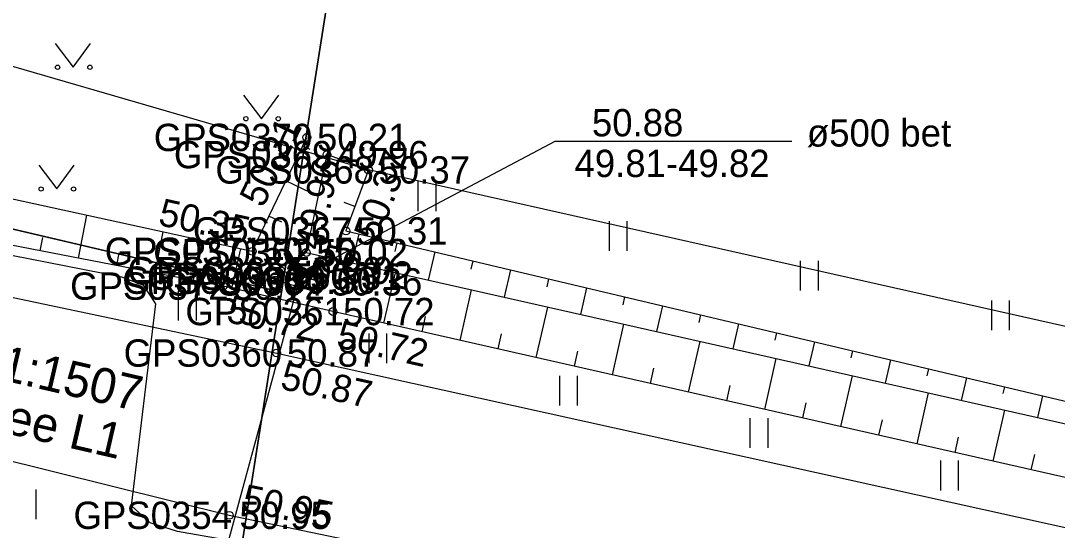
# Model space of a CAD drawing. Extents: x 551623 to 559850, y 6561220 to 6567135.
# Drawn here: x 555686.72 to 555713.27, y 6565381.27 to 6565394.32 of the extents above; entities that cross this region are included whole.
import ezdxf

# ---------------------------------------------------------------- set-up
doc = ezdxf.new("R2010")
doc.units = 0
for name, color, linetype in [('HALJASTUS', 7, 'Continuous'), ('KORGUS-EH2000', 7, 'Continuous'), ('MOOTKORG-EH2000', 7, 'Continuous'), ('MOOTMPUNKT', 7, 'Continuous'), ('MOOTNR', 7, 'Continuous'), ('MOOTPIIR', 7, 'Continuous'), ('MPKAABEL', 7, 'Continuous'), ('PIIR', 7, 'Continuous'), ('RELJEEF', 7, 'Continuous'), ('TEE', 7, 'Continuous'), ('TRUUP', 7, 'Continuous')]:
    doc.layers.add(name, color=color, linetype=linetype)

msp = doc.modelspace()

# ---------------------------------------------------------------- linework, layer by layer
at = {"layer": 'HALJASTUS'}
for p, q in [((555687.602, 6565393.734), (555688.066, 6565393.127)), ((555688.066, 6565393.127), (555688.511, 6565393.734)), ((555692.425, 6565392.416), (555692.889, 6565391.809)), ((555692.889, 6565391.809), (555693.334, 6565392.416)), ((555687.183, 6565390.618), (555687.646, 6565390.011)), ((555687.646, 6565390.011), (555688.092, 6565390.618)), ((555696.897, 6565390.204), (555696.897, 6565389.443)), ((555697.352, 6565390.204), (555697.352, 6565389.443)), ((555701.793, 6565389.189), (555701.793, 6565388.428)), ((555702.248, 6565389.189), (555702.248, 6565388.428)), ((555706.689, 6565388.173), (555706.689, 6565387.412)), ((555707.144, 6565388.173), (555707.144, 6565387.412)), ((555690.758, 6565387.402), (555690.758, 6565386.641)), ((555691.213, 6565387.402), (555691.213, 6565386.641)), ((555711.584, 6565387.158), (555711.584, 6565386.397)), ((555712.04, 6565387.158), (555712.04, 6565386.397)), ((555695.638, 6565386.31), (555695.638, 6565385.549)), ((555696.093, 6565386.31), (555696.093, 6565385.549)), ((555700.519, 6565385.225), (555700.519, 6565384.464)), ((555700.974, 6565385.225), (555700.974, 6565384.464)), ((555705.399, 6565384.14), (555705.399, 6565383.379)), ((555705.854, 6565384.14), (555705.854, 6565383.379)), ((555710.28, 6565383.055), (555710.28, 6565382.294)), ((555710.735, 6565383.055), (555710.735, 6565382.294)), ((555687.109, 6565382.317), (555687.109, 6565381.556))]:
    msp.add_line(p, q, dxfattribs=at)
for centre in [(555687.665, 6565393.127), (555688.493, 6565393.127), (555692.488, 6565391.809), (555693.317, 6565391.809), (555687.245, 6565390.011), (555688.074, 6565390.011)]:
    msp.add_circle(centre, 0.055, dxfattribs=at)
at = {"layer": 'KORGUS-EH2000'}
for centre in [(555694.05, 6565391.331), (555694.565, 6565390.891), (555695.628, 6565390.499), (555692.652, 6565388.415), (555694.035, 6565388.383), (555691.907, 6565387.524), (555694.718, 6565386.873), (555693.278, 6565385.81), (555692.063, 6565381.655)]:
    msp.add_circle(centre, 0.1, dxfattribs=at)
at = {"layer": 'MOOTMPUNKT'}
for centre in [(555694.05, 6565391.331), (555694.565, 6565390.891), (555695.628, 6565390.499), (555695.052, 6565388.937), (555692.652, 6565388.415), (555694.035, 6565388.383), (555693.378, 6565387.919), (555693.875, 6565387.778), (555691.907, 6565387.524), (555693.243, 6565387.677), (555694.404, 6565387.632), (555694.718, 6565386.873), (555693.278, 6565385.81), (555692.063, 6565381.655)]:
    msp.add_circle(centre, 0.1, dxfattribs=at)
at = {"layer": 'MOOTPIIR'}
msp.add_lwpolyline([(555870.644, 6565361.764), (555852.219, 6565361.421), (555851.243, 6565363.431), (555851.072, 6565365.834), (555850.919, 6565369.424), (555850.689, 6565372.676), (555824.92, 6565373.681), (555819.298, 6565374.346), (555817.733, 6565372.559), (555794.391, 6565373.752), (555774.303, 6565374.86), (555767.052, 6565376.433), (555763.583, 6565376.705), (555741.853, 6565379.526), (555720.243, 6565384.972), (555695.628, 6565390.499), (555681.099, 6565394.714), (555669.53, 6565398.005), (555662.804, 6565398.822)], dxfattribs=at)
at = {"layer": 'MPKAABEL'}
msp.add_lwpolyline([(555754.809, 6565368.578), (555745.82, 6565370.031), (555736.449, 6565371.941), (555727.141, 6565373.859), (555717.551, 6565375.859), (555708.191, 6565377.73), (555698.129, 6565379.941), (555690.738, 6565381.238), (555690.039, 6565381.461), (555689.559, 6565381.898), (555690.18, 6565387.07), (555689.871, 6565387.539), (555689.309, 6565387.75), (555680.781, 6565389.43), (555671.469, 6565391.391), (555661.898, 6565393.719)], dxfattribs=at)
at = {"layer": 'PIIR'}
for points in [[(555584.65, 6565412.91), (555612.09, 6565586.3), (555722.09, 6565569.1), (555693.4, 6565387.37)], [(555693.4, 6565387.37), (555722.09, 6565569.1), (555756.75, 6565564.43), (555823.05, 6565554.69), (555792.17, 6565359.86), (555785.15, 6565359.9), (555766.77, 6565362.31), (555692.03, 6565378.6)], [(555443.35, 6565442.49), (555368.05, 6565461.11), (555419.74, 6565450.66), (555470.4, 6565439.4), (555495.41, 6565433.85), (555584.65, 6565412.91), (555693.4, 6565387.37), (555692.03, 6565378.6), (555540.46, 6565411.94), (555441.38, 6565433.61)]]:
    msp.add_lwpolyline(points, close=True, dxfattribs=at)
at = {"layer": 'RELJEEF'}
for p, q in [((555692.652, 6565388.415), (555694.05, 6565391.331)), ((555693.949, 6565391.12), (555694.13, 6565391.034)), ((555695.628, 6565390.499), (555694.565, 6565390.891)), ((555693.517, 6565390.219), (555694.34, 6565389.824)), ((555695.282, 6565389.561), (555695.004, 6565389.663)), ((555688.202, 6565388.239), (555688.415, 6565389.34)), ((555693.084, 6565389.317), (555693.397, 6565389.167)), ((555690.166, 6565387.86), (555690.369, 6565388.913)), ((555687.22, 6565388.428), (555687.285, 6565388.766)), ((555695.378, 6565388.86), (555695.203, 6565388.119)), ((555696.352, 6565388.63), (555696.3, 6565388.411)), ((555689.184, 6565388.049), (555689.246, 6565388.372)), ((555692.128, 6565387.472), (555692.361, 6565388.479)), ((555697.325, 6565388.399), (555697.154, 6565387.679)), ((555694.229, 6565387.681), (555694.373, 6565388.306)), ((555698.298, 6565388.169), (555698.247, 6565387.956)), ((555691.148, 6565387.67), (555691.207, 6565387.979)), ((555696.026, 6565386.577), (555696.319, 6565387.868)), ((555699.271, 6565387.939), (555699.105, 6565387.239)), ((555700.244, 6565387.708), (555700.195, 6565387.502)), ((555694.076, 6565387.022), (555694.168, 6565387.418)), ((555697.977, 6565386.135), (555698.27, 6565387.428)), ((555701.217, 6565387.478), (555701.056, 6565386.799)), ((555695.051, 6565386.798), (555695.139, 6565387.185)), ((555702.19, 6565387.248), (555702.143, 6565387.047)), ((555703.163, 6565387.017), (555703.007, 6565386.359)), ((555699.927, 6565385.693), (555700.221, 6565386.987)), ((555704.136, 6565386.787), (555704.09, 6565386.593)), ((555697.002, 6565386.356), (555697.089, 6565386.743)), ((555701.878, 6565385.251), (555702.172, 6565386.547)), ((555705.11, 6565386.557), (555704.959, 6565385.919)), ((555698.952, 6565385.914), (555699.04, 6565386.302)), ((555706.083, 6565386.326), (555706.038, 6565386.138)), ((555703.829, 6565384.81), (555704.123, 6565386.107)), ((555707.056, 6565386.096), (555706.91, 6565385.479)), ((555700.903, 6565385.472), (555700.991, 6565385.861)), ((555708.029, 6565385.866), (555707.986, 6565385.683)), ((555705.779, 6565384.368), (555706.073, 6565385.667)), ((555709.002, 6565385.635), (555708.861, 6565385.038)), ((555702.853, 6565385.031), (555702.941, 6565385.42)), ((555707.73, 6565383.926), (555708.024, 6565385.227)), ((555709.975, 6565385.405), (555709.933, 6565385.229)), ((555710.948, 6565385.175), (555710.812, 6565384.598)), ((555704.804, 6565384.589), (555704.892, 6565384.978)), ((555711.921, 6565384.944), (555711.881, 6565384.774)), ((555709.68, 6565383.484), (555709.975, 6565384.787)), ((555712.894, 6565384.714), (555712.763, 6565384.158)), ((555706.755, 6565384.147), (555706.843, 6565384.537)), ((555708.705, 6565383.705), (555708.794, 6565384.096)), ((555711.631, 6565383.042), (555711.926, 6565384.347)), ((555710.656, 6565383.263), (555710.744, 6565383.654)), ((555712.606, 6565382.822), (555712.695, 6565383.213))]:
    msp.add_line(p, q, dxfattribs=at)
for points in [[(555670.328, 6565392.887), (555679.228, 6565391.344), (555692.652, 6565388.415)], [(555695.628, 6565390.499), (555695.052, 6565388.937), (555720.222, 6565382.979), (555741.364, 6565378.247), (555757.349, 6565375.192), (555755.723, 6565374.838), (555741.151, 6565377.01), (555719.315, 6565381.302), (555694.718, 6565386.873), (555691.907, 6565387.524), (555678.96, 6565390.023), (555670.827, 6565391.88), (555670.328, 6565392.887)], [(555694.565, 6565390.891), (555694.035, 6565388.383), (555719.805, 6565382.57), (555741.241, 6565377.86), (555757.349, 6565375.192)]]:
    msp.add_lwpolyline(points, dxfattribs=at)
at = {"layer": 'TEE'}
for points in [[(555463.469, 6565434.873), (555479.318, 6565431.962), (555490.115, 6565429.76), (555497.95, 6565427.828), (555519.263, 6565422.564), (555542.613, 6565417.073), (555565.599, 6565412.035), (555589.51, 6565406.357), (555610.656, 6565401.422), (555635.154, 6565395.619), (555656.789, 6565389.809), (555677.01, 6565385.399), (555692.063, 6565381.655), (555718.607, 6565376.133), (555737.61, 6565372.216), (555759.321, 6565368.781), (555773.34, 6565367.27), (555785.196, 6565366.246), (555799.302, 6565365.674), (555824.141, 6565365.476), (555838.654, 6565365.624), (555851.072, 6565365.834)], [(555669.53, 6565398.005), (555669.393, 6565393.924), (555669.794, 6565392.158), (555670.453, 6565390.974), (555678.315, 6565388.964), (555693.278, 6565385.81), (555719.15, 6565380.087), (555738.319, 6565376.143), (555759.458, 6565372.557), (555763.069, 6565372.038), (555773.873, 6565370.985), (555785.453, 6565370.072), (555799.764, 6565369.552), (555819.003, 6565369.583), (555821.106, 6565370.429), (555821.559, 6565371.986), (555822.022, 6565373.687)]]:
    msp.add_lwpolyline(points, dxfattribs=at)
at = {"layer": 'TRUUP'}
for p, q in [((555693.585, 6565388.427), (555693.461, 6565388.356)), ((555693.461, 6565388.356), (555693.848, 6565387.681)), ((555693.487, 6565388.371), (555693.49, 6565388.305)), ((555693.511, 6565388.385), (555693.518, 6565388.257)), ((555693.523, 6565388.391), (555693.875, 6565387.778)), ((555693.535, 6565388.398), (555693.545, 6565388.209)), ((555693.559, 6565388.412), (555693.573, 6565388.161)), ((555693.584, 6565388.426), (555693.601, 6565388.113)), ((555693.585, 6565388.427), (555693.901, 6565387.875)), ((555693.611, 6565388.38), (555693.628, 6565388.064)), ((555693.639, 6565388.332), (555693.656, 6565388.016)), ((555693.666, 6565388.284), (555693.683, 6565387.968)), ((555693.694, 6565388.236), (555693.711, 6565387.92)), ((555693.722, 6565388.188), (555693.739, 6565387.872)), ((555693.749, 6565388.139), (555693.766, 6565387.823)), ((555693.777, 6565388.091), (555693.794, 6565387.775)), ((555693.875, 6565387.778), (555694.488, 6565388.13)), ((555693.901, 6565387.875), (555694.453, 6565388.191)), ((555694.278, 6565388.091), (555694.286, 6565387.932)), ((555694.302, 6565388.105), (555694.311, 6565387.946)), ((555694.326, 6565388.119), (555694.335, 6565387.96)), ((555694.351, 6565388.133), (555694.359, 6565387.974)), ((555694.375, 6565388.147), (555694.383, 6565387.988)), ((555694.399, 6565388.161), (555694.408, 6565388.002)), ((555694.423, 6565388.175), (555694.432, 6565388.016)), ((555694.448, 6565388.189), (555694.456, 6565388.03)), ((555694.453, 6565388.191), (555694.523, 6565388.068)), ((555694.475, 6565388.153), (555694.481, 6565388.043)), ((555694.502, 6565388.105), (555694.505, 6565388.057)), ((555693.805, 6565388.043), (555693.822, 6565387.727)), ((555693.832, 6565387.995), (555693.849, 6565387.681)), ((555693.848, 6565387.681), (555694.523, 6565388.068)), ((555693.86, 6565387.947), (555693.873, 6565387.695)), ((555693.888, 6565387.898), (555693.898, 6565387.709)), ((555693.913, 6565387.882), (555693.922, 6565387.723)), ((555693.938, 6565387.896), (555693.946, 6565387.737)), ((555693.962, 6565387.91), (555693.971, 6565387.751)), ((555693.986, 6565387.924), (555693.995, 6565387.765)), ((555694.011, 6565387.938), (555694.019, 6565387.779)), ((555694.035, 6565387.952), (555694.043, 6565387.793)), ((555694.059, 6565387.966), (555694.068, 6565387.807)), ((555694.083, 6565387.98), (555694.092, 6565387.821)), ((555694.108, 6565387.994), (555694.116, 6565387.835)), ((555694.132, 6565388.008), (555694.141, 6565387.848)), ((555694.156, 6565388.022), (555694.165, 6565387.862)), ((555694.181, 6565388.036), (555694.189, 6565387.876)), ((555694.205, 6565388.049), (555694.213, 6565387.89)), ((555694.229, 6565388.063), (555694.238, 6565387.904)), ((555694.253, 6565388.077), (555694.262, 6565387.918)), ((555693.875, 6565387.78), (555691.37, 6565378.542))]:
    msp.add_line(p, q, dxfattribs=at)
msp.add_lwpolyline([(555693.875, 6565387.78), (555700.412, 6565391.238), (555706.469, 6565391.238)], dxfattribs=at)
msp.add_lwpolyline([(555694.404, 6565387.632), (555693.378, 6565387.919), (555693.306, 6565387.659), (555694.332, 6565387.372)], close=True, dxfattribs=at)

# ---------------------------------------------------------------- texts
at = {"layer": 'KORGUS-EH2000'}
for s, rotation, p in [(' 50.21', 64.3773, (555692.815, 6565389.269)), (' 50.37', 69.759, (555695.801, 6565388.389)), (' 49.96', 78.0685, (555694.371, 6565388.164)), (' 50.35', 347.6916, (555689.962, 6565389.149)), (' 50.02', 347.2881, (555694.103, 6565387.986)), (' 50.72', 346.9767, (555691.709, 6565386.671)), (' 50.72', 347.2381, (555694.524, 6565386.02)), (' 50.87', 347.5281, (555693.089, 6565384.955)), (' 50.95', 348.2501, (555692.098, 6565381.826))]:
    msp.add_text(s, height=0.7, rotation=rotation, dxfattribs=at).set_placement(p)
at = {"layer": 'MOOTKORG-EH2000'}
for s, p in [(' 50.21', (555694.05, 6565390.981)), (' 49.96', (555694.565, 6565390.541)), (' 50.37', (555695.628, 6565390.149)), (' 50.31', (555695.052, 6565388.587)), (' 50.35', (555692.652, 6565388.065)), (' 50.02', (555694.035, 6565388.033)), (' 50.30', (555693.378, 6565387.569)), (' 50.31', (555693.875, 6565387.428)), (' 50.72', (555691.907, 6565387.174)), (' 50.60', (555693.243, 6565387.326)), (' 50.36', (555694.404, 6565387.282)), (' 50.72', (555694.718, 6565386.523)), (' 50.87', (555693.278, 6565385.46)), (' 50.95', (555692.063, 6565381.305))]:
    msp.add_text(s, height=0.7, dxfattribs=at).set_placement(p)
at = {"layer": 'MOOTNR'}
for s, p in [('GPS0370 ', (555690.13, 6565390.981)), ('GPS0369 ', (555690.645, 6565390.541)), ('GPS0368 ', (555691.708, 6565390.149)), ('GPS0367 ', (555691.132, 6565388.587)), ('GPS0371 ', (555688.872, 6565388.065)), ('GPS0362 ', (555690.115, 6565388.033)), ('GPS0365 ', (555689.459, 6565387.569)), ('GPS0363 ', (555689.955, 6565387.428)), ('GPS0372 ', (555687.987, 6565387.174)), ('GPS0366 ', (555689.323, 6565387.326)), ('GPS0364 ', (555690.414, 6565387.282)), ('GPS0361 ', (555690.938, 6565386.523)), ('GPS0360 ', (555689.358, 6565385.46)), ('GPS0354 ', (555688.073, 6565381.305))]:
    msp.add_text(s, height=0.7, dxfattribs=at).set_placement(p)
at = {"layer": 'PIIR'}
for s, p in [('33801:001:1507', (555681.236, 6565386.273)), ('Sommeri tee L1', (555680.943, 6565385.006))]:
    msp.add_text(s, height=0.9, rotation=346.9809, dxfattribs=at).set_placement(p)
at = {"layer": 'TRUUP'}
for s, p in [('50.88', (555701.352, 6565391.358)), ('ø500 bet', (555706.858, 6565391.097)), ('49.81-49.82', (555700.906, 6565390.316))]:
    msp.add_text(s, height=0.7, dxfattribs=at).set_placement(p)

doc.saveas('drawing.dxf')
